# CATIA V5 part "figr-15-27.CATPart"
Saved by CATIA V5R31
Part number: Part1
Bounding box of the stored display mesh (mm): x -61.282 to 61.282, y -26.72 to 26.72, z 0 to 0.75
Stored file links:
  D:\PROJECTS\Project 2021\US EDITION\CATIA V5 6R 2021\Resources\Part Files\c15_catia_v5_6r2021_prt\figr-15-27.CATPart
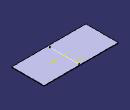
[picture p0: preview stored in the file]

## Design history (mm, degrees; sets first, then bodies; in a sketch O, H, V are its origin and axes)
SheetMetalParameters1: Thickness 0.75, BendRadius 1, KFactor 0.356492 {= log(min(100,max(20*SheetMetalParameters1.BendRadius,SheetMetalParameters1.Thickness)/SheetMetalParameters1.Thickness))/log(100)/2}, ReliefRadialLength 1, ReliefAxialLength 2, MinimumBendRadius 0
Body1 (main body)
  Sketch1 on xy-plane, origin (0, 0, 0), H (1, 0, 0), V (0, 1, 0)
    line L1 (61.282, 26.7197) -> (61.282, -26.7197)
    line L2 (61.282, -26.7197) -> (-61.282, -26.7197)
    line L3 (-61.282, -26.7197) -> (-61.282, 26.7197)
    line L4 (-61.282, 26.7197) -> (61.282, 26.7197)
    vertical: L1 V, L3 V
    horizontal: L2 H, L4 H
    equidistance: L1 L3 O, L2 L4 O
  Wall1: Thickness 0.75, Profile Sketch1
  Sketch2 on face of Wall1, origin (0, 0, 0.75), H (1, 0, 0), V (0, 1, 0)
    line L1 (1.9015, 25.4615) -> (1.9015, -22.9675)
    vertical: L1 V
